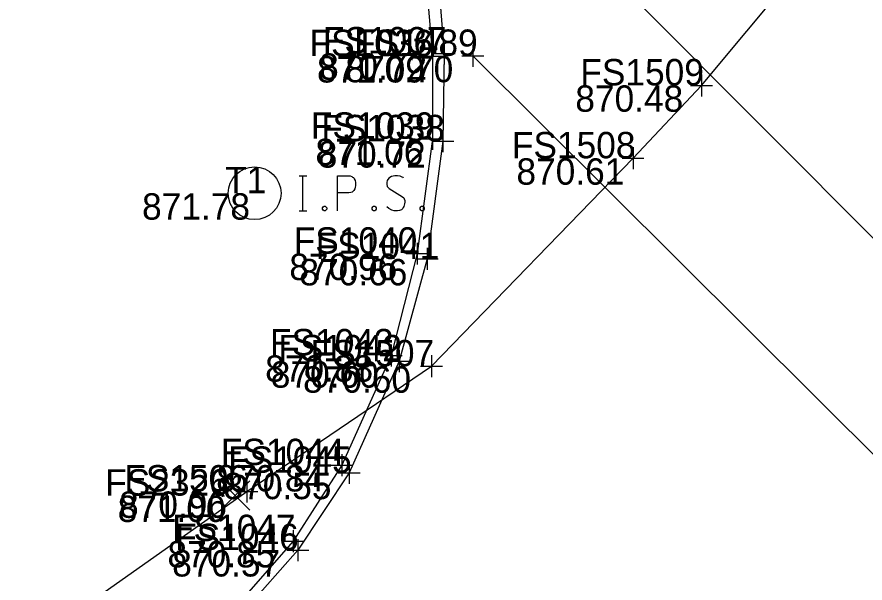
# Model space of a CAD drawing. Extents: x 1479420 to 1479833, y 379731 to 380103.
# Drawn here: x 1479554.39 to 1479592.95, y 379907.15 to 379932.9 of the extents above; entities that cross this region are included whole.
import ezdxf

# ---------------------------------------------------------------- set-up
doc = ezdxf.new("R2010")
doc.units = 0
for name, color, linetype in [('PM_X_Crosswalk', 7, 'Continuous'), ('PV_X_Curb', 7, 'Continuous'), ('SV_P_Mon_Cells_Set', 7, 'Continuous'), ('SV_X_Random_Point', 7, 'Continuous'), ('SV_X_Shot_Marker', 7, 'Continuous'), ('SV_X_Text_Elevation', 7, 'Continuous'), ('SV_X_Text_Name', 7, 'Continuous'), ('UT_X_Water', 7, 'Continuous')]:
    doc.layers.add(name, color=color, linetype=linetype)

msp = doc.modelspace()

# ---------------------------------------------------------------- linework, layer by layer
at = {"layer": 'PM_X_Crosswalk'}
for p, q in [((1479636.371, 379879.555), (1479574.01, 379942.241)), ((1479627.792, 379878.685), (1479575.124, 379931.128))]:
    msp.add_line(p, q, dxfattribs=at)
at = {"layer": 'PV_X_Curb'}
for points in [[(1479465.43, 380051.173), (1479478.923, 380037.911), (1479495.631, 380021.426), (1479511.639, 380005.785), (1479526.613, 379991.238), (1479541.434, 379976.722), (1479556.225, 379962.402), (1479558.522, 379960.088), (1479562.263, 379956.631), (1479564.944, 379953.172), (1479567.55, 379949.792), (1479570.394, 379944.783), (1479571.863, 379941.541), (1479572.44, 379940.294), (1479572.888, 379938.328), (1479573.209, 379936.746), (1479573.486, 379935.414), (1479573.818, 379931.241), (1479573.756, 379927.245), (1479573.045, 379921.888), (1479571.771, 379917.234), (1479569.497, 379912.161), (1479567.166, 379908.643), (1479563.944, 379905.002)], [(1479465.217, 380050.646), (1479478.531, 380037.631), (1479495.524, 380020.938), (1479511.459, 380005.334), (1479526.353, 379990.752), (1479540.932, 379976.569), (1479555.934, 379961.972), (1479555.892, 379961.631), (1479559.685, 379957.777), (1479564.545, 379952.777), (1479567.017, 379949.687), (1479570.003, 379944.359), (1479571.368, 379941.515), (1479571.64, 379940.628), (1479572.403, 379938.2), (1479572.729, 379936.736), (1479572.917, 379935.416), (1479573.286, 379931.116), (1479573.281, 379927.358), (1479572.586, 379922.13), (1479571.403, 379917.504), (1479569.157, 379912.511), (1479566.948, 379909.055), (1479563.851, 379905.522)]]:
    msp.add_lwpolyline(points, dxfattribs=at)
at = {"layer": 'SV_P_Mon_Cells_Set'}
for points in [[(1479567.217, 379925.678), (1479567.57, 379925.678)], [(1479567.393, 379924.078), (1479567.393, 379925.678)], [(1479568.959, 379924.078), (1479568.959, 379925.678), (1479569.488, 379925.678), (1479569.543, 379925.665), (1479569.62, 379925.64), (1479569.653, 379925.615), (1479569.686, 379925.59), (1479569.73, 379925.527), (1479569.763, 379925.464), (1479569.785, 379925.363), (1479569.785, 379925.212), (1479569.774, 379925.162), (1479569.752, 379925.086), (1479569.708, 379924.998), (1479569.664, 379924.96), (1479569.631, 379924.935), (1479569.576, 379924.91), (1479569.488, 379924.897), (1479568.959, 379924.897)], [(1479571.968, 379925.565), (1479571.946, 379925.59), (1479571.913, 379925.615), (1479571.814, 379925.653), (1479571.692, 379925.678), (1479571.604, 379925.678), (1479571.571, 379925.678), (1479571.428, 379925.64), (1479571.307, 379925.565), (1479571.229, 379925.464), (1479571.207, 379925.363), (1479571.207, 379925.288), (1479571.229, 379925.187), (1479571.318, 379925.099), (1479571.924, 379924.721), (1479571.979, 379924.67), (1479572.001, 379924.62), (1479572.023, 379924.544), (1479572.023, 379924.469), (1479572.012, 379924.393), (1479572.001, 379924.343), (1479571.979, 379924.28), (1479571.957, 379924.229), (1479571.935, 379924.192), (1479571.902, 379924.154), (1479571.869, 379924.129), (1479571.825, 379924.103), (1479571.792, 379924.091), (1479571.692, 379924.078), (1479571.538, 379924.078), (1479571.439, 379924.103), (1479571.295, 379924.192), (1479571.207, 379924.267)], [(1479567.217, 379924.078), (1479567.57, 379924.078)], [(1479568.352, 379924.292), (1479568.407, 379924.292), (1479568.441, 379924.267), (1479568.474, 379924.217), (1479568.474, 379924.154), (1479568.441, 379924.103), (1479568.407, 379924.078), (1479568.352, 379924.078), (1479568.319, 379924.103), (1479568.286, 379924.154), (1479568.286, 379924.217), (1479568.319, 379924.267), (1479568.352, 379924.292)], [(1479570.601, 379924.292), (1479570.656, 379924.292), (1479570.689, 379924.267), (1479570.722, 379924.217), (1479570.722, 379924.154), (1479570.689, 379924.103), (1479570.656, 379924.078), (1479570.601, 379924.078), (1479570.568, 379924.103), (1479570.535, 379924.154), (1479570.535, 379924.217), (1479570.568, 379924.267), (1479570.601, 379924.292)], [(1479572.784, 379924.292), (1479572.839, 379924.292), (1479572.872, 379924.267), (1479572.905, 379924.217), (1479572.905, 379924.154), (1479572.872, 379924.103), (1479572.839, 379924.078), (1479572.784, 379924.078), (1479572.75, 379924.103), (1479572.718, 379924.154), (1479572.718, 379924.217), (1479572.75, 379924.267), (1479572.784, 379924.292)]]:
    msp.add_lwpolyline(points, dxfattribs=at)
msp.add_circle((1479565.198, 379924.877), 1.2, dxfattribs=at)
at = {"layer": 'SV_X_Random_Point'}
for p, q in [((1479563.648, 379910.457), (1479564.982, 379911.792)), ((1479563.648, 379911.792), (1479564.982, 379910.457))]:
    msp.add_line(p, q, dxfattribs=at)
at = {"layer": 'SV_X_Shot_Marker'}
for p, q in [((1479573.286, 379931.616), (1479573.286, 379930.616)), ((1479573.818, 379931.741), (1479573.818, 379930.741)), ((1479575.124, 379931.628), (1479575.124, 379930.628)), ((1479572.786, 379931.116), (1479573.786, 379931.116)), ((1479573.286, 379931.116), (1479573.286, 379931.116)), ((1479573.318, 379931.241), (1479574.318, 379931.241)), ((1479573.818, 379931.241), (1479573.818, 379931.241)), ((1479574.624, 379931.128), (1479575.624, 379931.128)), ((1479575.124, 379931.128), (1479575.124, 379931.128)), ((1479585.515, 379930.286), (1479585.515, 379929.286)), ((1479585.015, 379929.786), (1479586.015, 379929.786)), ((1479585.515, 379929.786), (1479585.515, 379929.786)), ((1479573.281, 379927.858), (1479573.281, 379926.858)), ((1479573.756, 379927.745), (1479573.756, 379926.745)), ((1479572.781, 379927.358), (1479573.781, 379927.358)), ((1479573.256, 379927.245), (1479574.256, 379927.245)), ((1479573.281, 379927.358), (1479573.281, 379927.358)), ((1479573.756, 379927.245), (1479573.756, 379927.245)), ((1479582.403, 379926.968), (1479582.403, 379925.968)), ((1479581.903, 379926.468), (1479582.903, 379926.468)), ((1479582.403, 379926.468), (1479582.403, 379926.468)), ((1479572.586, 379922.63), (1479572.586, 379921.63)), ((1479572.086, 379922.13), (1479573.086, 379922.13)), ((1479572.586, 379922.13), (1479572.586, 379922.13)), ((1479573.045, 379922.388), (1479573.045, 379921.388)), ((1479572.545, 379921.888), (1479573.545, 379921.888)), ((1479573.045, 379921.888), (1479573.045, 379921.888)), ((1479571.403, 379918.004), (1479571.403, 379917.004)), ((1479570.903, 379917.504), (1479571.903, 379917.504)), ((1479571.403, 379917.504), (1479571.403, 379917.504)), ((1479571.771, 379917.734), (1479571.771, 379916.734)), ((1479573.24, 379917.505), (1479573.24, 379916.505)), ((1479571.271, 379917.234), (1479572.271, 379917.234)), ((1479571.771, 379917.234), (1479571.771, 379917.234)), ((1479572.74, 379917.005), (1479573.74, 379917.005)), ((1479573.24, 379917.005), (1479573.24, 379917.005)), ((1479569.157, 379913.011), (1479569.157, 379912.011)), ((1479568.657, 379912.511), (1479569.657, 379912.511)), ((1479569.157, 379912.511), (1479569.157, 379912.511)), ((1479569.497, 379912.661), (1479569.497, 379911.661)), ((1479568.997, 379912.161), (1479569.997, 379912.161)), ((1479569.497, 379912.161), (1479569.497, 379912.161)), ((1479564.844, 379911.811), (1479564.844, 379910.811)), ((1479564.344, 379911.311), (1479565.344, 379911.311)), ((1479564.844, 379911.311), (1479564.844, 379911.311)), ((1479566.948, 379909.555), (1479566.948, 379908.555)), ((1479566.448, 379909.055), (1479567.448, 379909.055)), ((1479566.948, 379909.055), (1479566.948, 379909.055)), ((1479567.166, 379909.143), (1479567.166, 379908.143)), ((1479566.666, 379908.643), (1479567.666, 379908.643)), ((1479567.166, 379908.643), (1479567.166, 379908.643))]:
    msp.add_line(p, q, dxfattribs=at)
at = {"layer": 'UT_X_Water'}
msp.add_lwpolyline([(1479451.52, 379837.183), (1479469.615, 379848.275), (1479481.983, 379856.402), (1479496.242, 379865.929), (1479520, 379881.305), (1479538.557, 379892.999), (1479553.442, 379903.409), (1479554.944, 379904.326), (1479564.844, 379911.311), (1479573.24, 379917.005), (1479582.403, 379926.468), (1479585.515, 379929.786), (1479589.646, 379934.736), (1479591.405, 379936.451), (1479593.775, 379939.334)], dxfattribs=at)

# ---------------------------------------------------------------- texts
at = {"layer": 'SV_X_Text_Elevation'}
for s, p in [('871.09', (1479568.033, 379929.916)), ('870.72', (1479568.13, 379930.041)), ('870.70', (1479569.323, 379929.928)), ('870.48', (1479579.78, 379928.586)), ('871.06', (1479567.962, 379926.158)), ('870.72', (1479568.068, 379926.045)), ('870.61', (1479577.102, 379925.268)), ('871.78', (1479560.078, 379923.677)), ('870.96', (1479566.775, 379920.93)), ('870.66', (1479567.234, 379920.688)), ('870.88', (1479565.677, 379916.304)), ('870.60', (1479565.932, 379916.034)), ('870.60', (1479567.401, 379915.805)), ('870.84', (1479563.45, 379911.311)), ('870.55', (1479563.781, 379910.961)), ('870.96', (1479559.033, 379910.111)), ('871.00', (1479558.968, 379909.924)), ('870.85', (1479561.232, 379907.855)), ('870.57', (1479561.45, 379907.443))]:
    msp.add_text(s, height=1.2, dxfattribs=at).set_placement(p)
at = {"layer": 'SV_X_Text_Name'}
for s, p in [('FS1036', (1479567.693, 379931.116)), ('FS1037', (1479568.301, 379931.241)), ('FS1489', (1479569.72, 379931.128)), ('FS1509', (1479580.007, 379929.786)), ('FS1039', (1479567.754, 379927.358)), ('FS1038', (1479568.229, 379927.245)), ('FS1508', (1479576.895, 379926.468)), ('T1', (1479563.856, 379924.877)), ('FS1040', (1479566.974, 379922.13)), ('FS1041', (1479567.971, 379921.888)), ('FS1043', (1479565.895, 379917.504)), ('FS1042', (1479566.273, 379917.234)), ('FS1507', (1479567.742, 379917.005)), ('FS1044', (1479563.659, 379912.511)), ('FS1045', (1479563.989, 379912.161)), ('FS1506', (1479559.27, 379911.311)), ('FS2326', (1479558.401, 379911.124)), ('FS1047', (1479561.44, 379909.055)), ('FS1046', (1479561.583, 379908.643))]:
    msp.add_text(s, height=1.2, dxfattribs=at).set_placement(p)

doc.saveas('drawing.dxf')
